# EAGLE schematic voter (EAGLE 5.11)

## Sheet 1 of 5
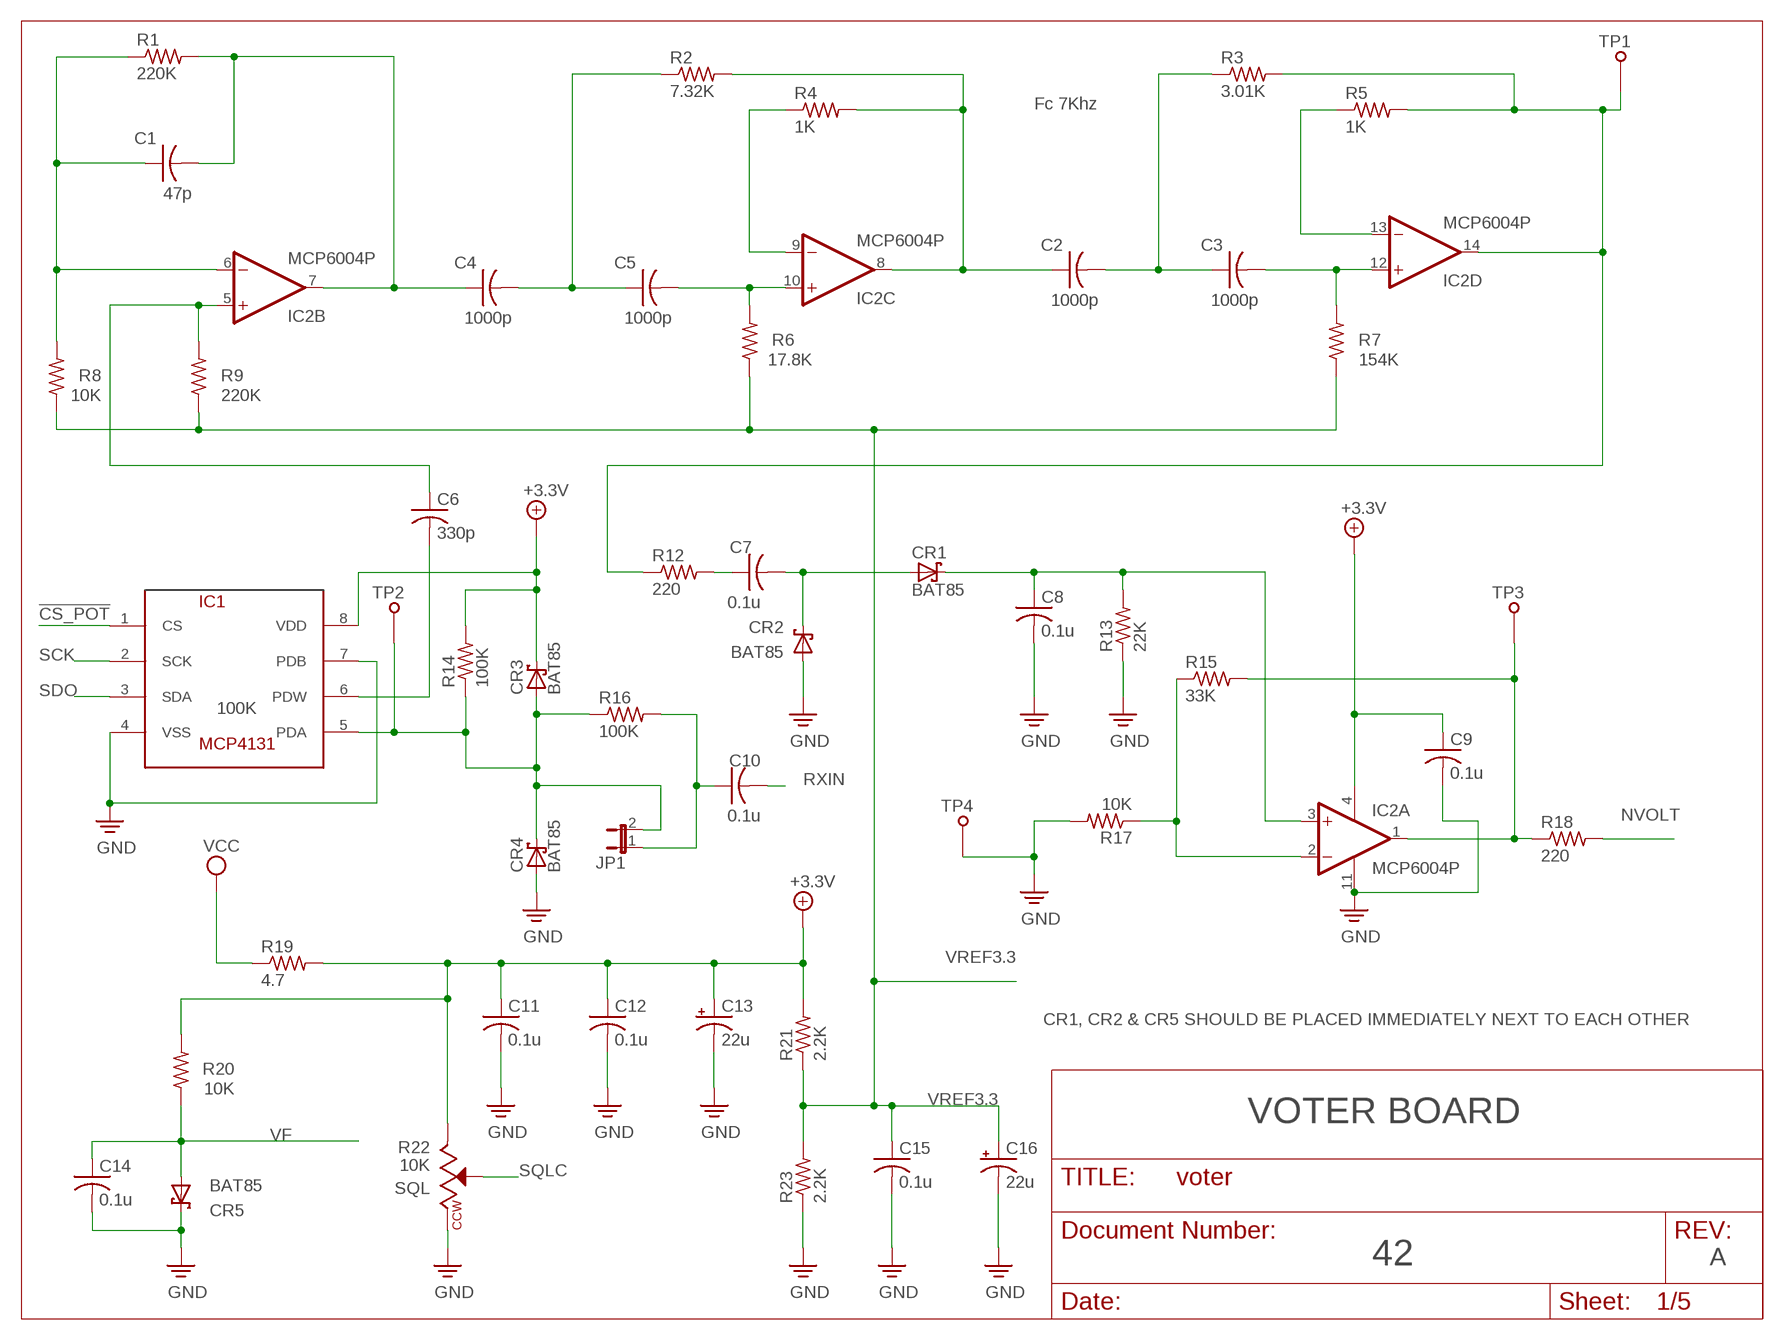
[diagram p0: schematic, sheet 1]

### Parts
C1  47p  C-US025-030X050  [C025-030X050]
C2  1000p  C-US025-030X050  [C025-030X050]
C3  1000p  C-US025-030X050  [C025-030X050]
C4  1000p  C-US025-030X050  [C025-030X050]
C5  1000p  C-US025-030X050  [C025-030X050]
C6  330p  C-US025-030X050  [C025-030X050]
C7  0.1u  C-US025-030X050  [C025-030X050]
C8  0.1u  C-US025-030X050  [C025-030X050]
C9  0.1u  C-US025-030X050  [C025-030X050]
C10  0.1u  C-US025-030X050  [C025-030X050]
C11  0.1u  C-US025-030X050  [C025-030X050]
C12  0.1u  C-US025-030X050  [C025-030X050]
C13  22u  CPOL-USE2-5  [E2-5]
C14  0.1u  C-US025-030X050  [C025-030X050]
C15  0.1u  C-US025-030X050  [C025-030X050]
C16  22u  CPOL-USE2-5  [E2-5]
CR1  BAT85  [DO34-7]
CR2  BAT85  [DO34-7]
CR3  BAT85  [DO34-7]
CR4  BAT85  [DO34-7]
CR5  BAT85  [DO34-7]
IC1  MCP4131  [DIL08]
IC2  MCP6004P  MCP604P  [DIL14]
JP1  JP1E  [JP1]
R1  220K  R-US_0207/10  [0207/10]
R2  7.32K  R-US_0207/10  [0207/10]
R3  3.01K  R-US_0207/10  [0207/10]
R4  1K  R-US_0207/10  [0207/10]
R5  1K  R-US_0207/10  [0207/10]
R6  17.8K  R-US_0207/10  [0207/10]
R7  154K  R-US_0207/10  [0207/10]
R8  10K  R-US_0207/10  [0207/10]
R9  220K  R-US_0207/10  [0207/10]
R12  220  R-US_0207/10  [0207/10]
R13  22K  R-US_0207/10  [0207/10]
R14  100K  R-US_0207/10  [0207/10]
R15  33K  R-US_0207/10  [0207/10]
R16  100K  R-US_0207/10  [0207/10]
R17  10K  R-US_0207/10  [0207/10]
R18  220  R-US_0207/10  [0207/10]
R19  4.7  R-US_0207/10  [0207/10]
R20  10K  R-US_0207/10  [0207/10]
R21  2.2K  R-US_0207/10  [0207/10]
R22  10K  BOURNS3296W  [BOURNS3296]
R23  2.2K  R-US_0207/10  [0207/10]
TP1  TESTPINTPSQ025  [TESTPIN]
TP2  TESTPINTPSQ025  [TESTPIN]
TP3  TESTPINTPSQ025  [TESTPIN]
TP4  TESTPINTPSQ025  [TESTPIN]

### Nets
!CS_POT: IC1.1(CS) ; also sheet 3
+3.3V [power]: C9.1 C11.1 C12.1 C13.+ CR3.C IC1.8(VDD) IC2.4(P:V+) R14.2 R19.2 R20.2 R21.2 R22.3 ; also sheet 2,3
FLTNOISE: IC2.14(D:OUT) R3.2 R5.2 R12.1 TP1.TP
GND: C8.2 C9.2 C11.2 C12.2 C13.- C14.2 C15.2 C16.- CR2.A CR4.A CR5.C IC1.4(VSS) IC1.7(PDB) IC2.11(P:V-) R13.1 R17.2 R22.1 R23.1 TP4.TP ; also sheet 2,3,4,5
N$1: IC2.2(A:-IN) R15.1 R17.1
N$3: C1.2 C4.1 IC2.7(B:OUT) R1.2
N$4: C4.2 C5.1 R2.1
N$5: C5.2 IC2.10(C:+IN) R6.2
N$6: C2.1 IC2.8(C:OUT) R2.2 R4.2
N$7: C2.2 C3.1 R3.1
N$8: C3.2 IC2.12(D:+IN) R7.2
N$9: C8.1 CR1.C IC2.3(A:+IN) R13.2
N$10: C1.1 IC2.6(B:-IN) R1.1 R8.2
N$11: C7.2 CR1.A CR2.C
N$12: IC2.13(D:-IN) R5.1
N$13: IC2.9(C:-IN) R4.1
N$14: CR3.A CR4.C IC1.5(PDA) JP1.2 R14.1 R16.1 TP2.TP
N$15: C10.1 JP1.1 R16.2
N$16: C7.1 R12.2
N$18: IC2.1(A:OUT) R15.2 R18.1 TP3.TP
N$19: C6.2 IC1.6(PDW)
N$23: C6.1 IC2.5(B:+IN) R9.2
NVOLT: R18.2 ; also sheet 3
RXIN: C10.2 ; also sheet 2,5
SCK: IC1.2(SCK) ; also sheet 3,4
SDO: IC1.3(SDA) ; also sheet 3,4
SQLC: R22.2 ; also sheet 3
VCC [power]: R19.1 ; also sheet 3,4,5
VF: C14.1 CR5.A R20.1 ; also sheet 3
VREF3.3: C15.1 C16.+ R6.1 R7.1 R8.1 R9.1 R21.1 R23.2 ; also sheet 2

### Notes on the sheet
- Fc 7Khz
- 100K
- VREF3.3
- CR1, CR2 & CR5 SHOULD BE PLACED IMMEDIATELY NEXT TO EACH OTHER
- VOTER BOARD
- SQL
- 42 | A

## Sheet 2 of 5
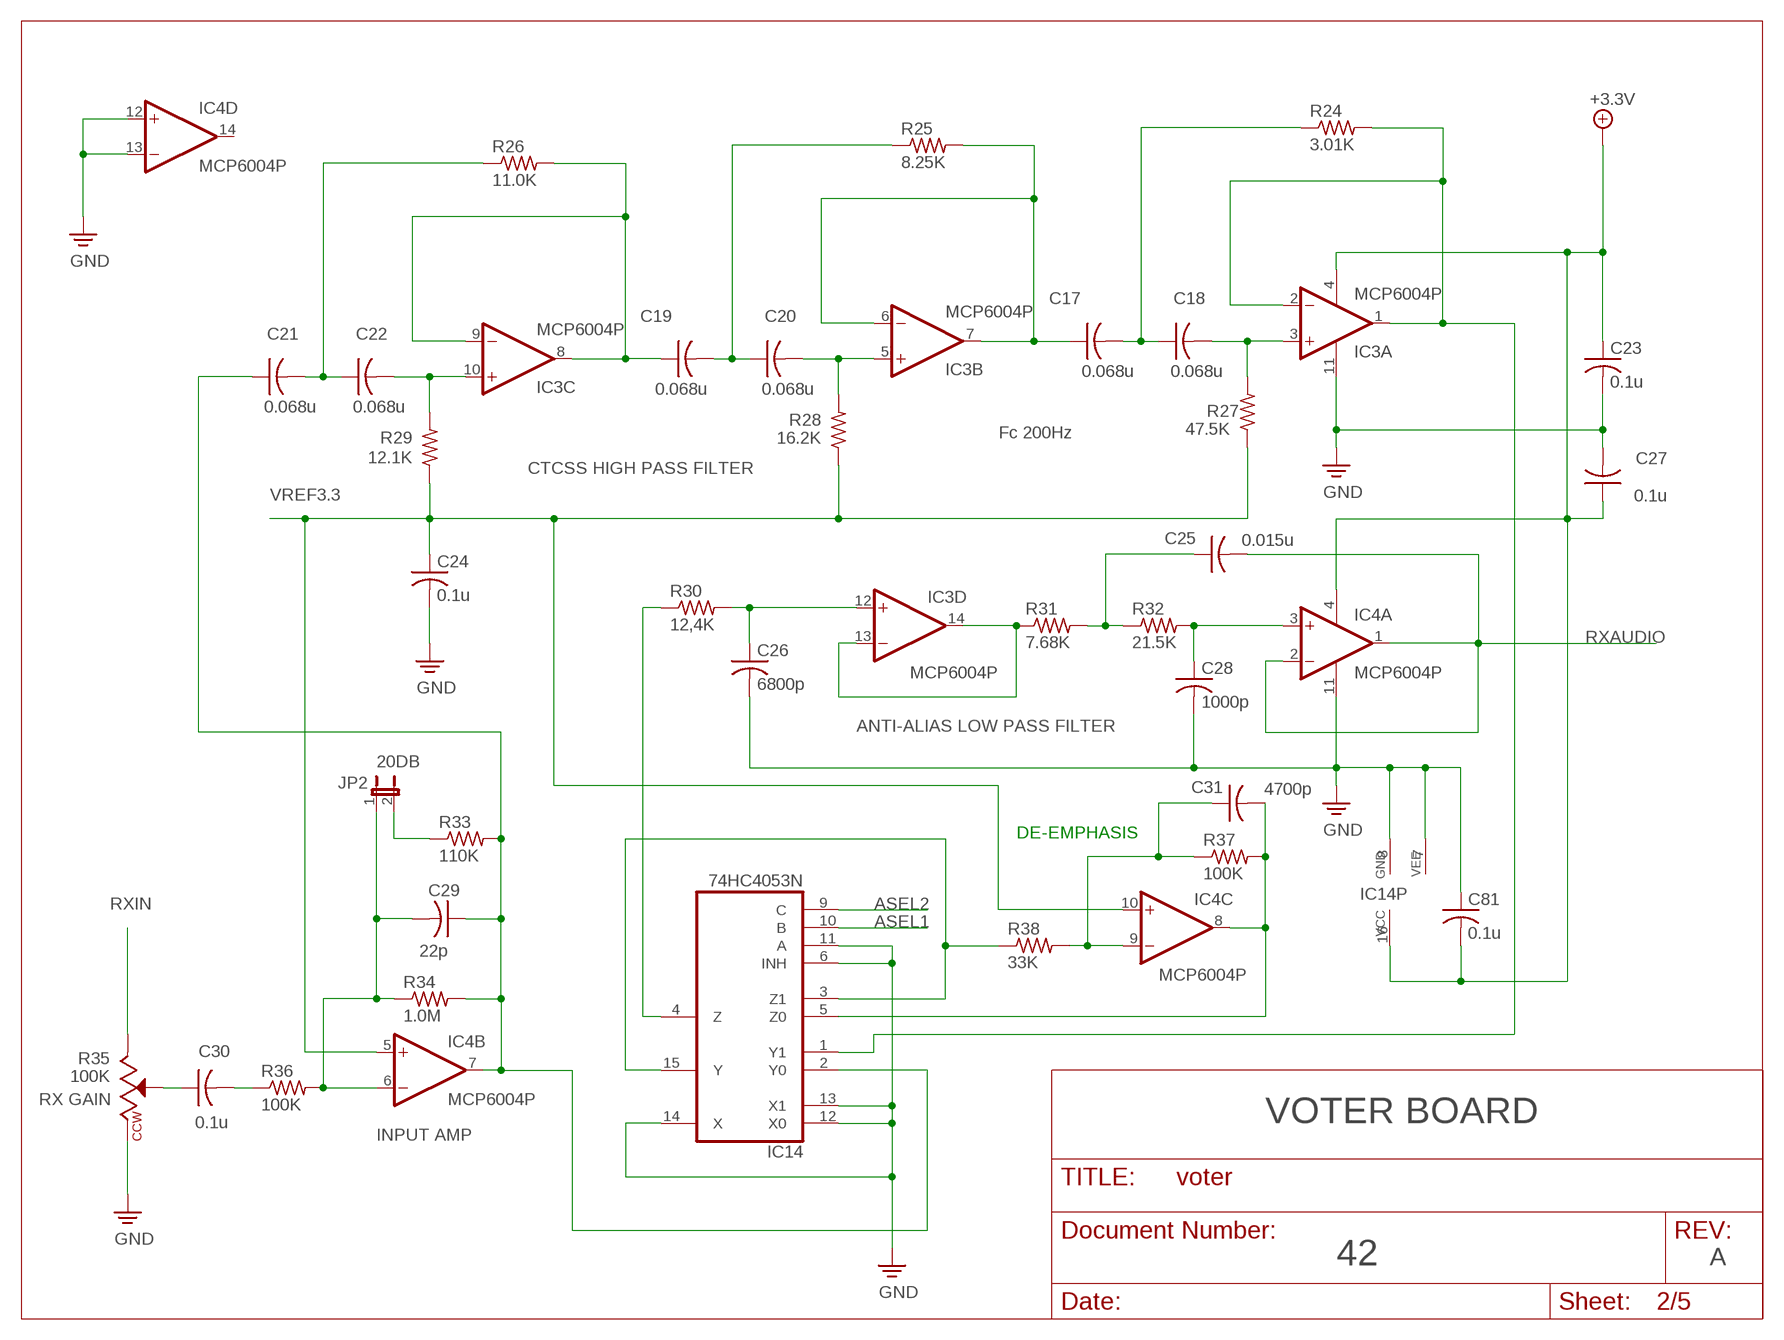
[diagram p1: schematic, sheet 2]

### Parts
C17  0.068u  C-US050-030X075  [C050-030X075]
C18  0.068u  C-US050-030X075  [C050-030X075]
C19  0.068u  C-US050-030X075  [C050-030X075]
C20  0.068u  C-US050-030X075  [C050-030X075]
C21  0.068u  C-US050-030X075  [C050-030X075]
C22  0.068u  C-US050-030X075  [C050-030X075]
C23  0.1u  C-US025-030X050  [C025-030X050]
C24  0.1u  C-US025-030X050  [C025-030X050]
C25  0.015u  C-US050-030X075  [C050-030X075]
C26  6800p  C-US050-030X075  [C050-030X075]
C27  0.1u  C-US025-030X050  [C025-030X050]
C28  1000p  C-US025-030X050  [C025-030X050]
C29  22p  C-US025-030X050  [C025-030X050]
C30  0.1u  C-US025-030X050  [C025-030X050]
C31  4700p  C-US050-030X075  [C050-030X075]
C81  0.1u  C-US025-030X050  [C025-030X050]
IC3  MCP6004P  MCP604P  [DIL14]
IC4  MCP6004P  MCP604P  [DIL14]
IC14  74HC4053N  4053N  [DIL16]
JP2  JP1E  [JP1]
R24  3.01K  R-US_0207/10  [0207/10]
R25  8.25K  R-US_0207/10  [0207/10]
R26  11.0K  R-US_0207/10  [0207/10]
R27  47.5K  R-US_0207/10  [0207/10]
R28  16.2K  R-US_0207/10  [0207/10]
R29  12.1K  R-US_0207/10  [0207/10]
R30  12,4K  R-US_0207/10  [0207/10]
R31  7.68K  R-US_0207/10  [0207/10]
R32  21.5K  R-US_0207/10  [0207/10]
R33  110K  R-US_0207/10  [0207/10]
R34  1.0M  R-US_0207/10  [0207/10]
R35  100K  BOURNS3296W  [BOURNS3296]
R36  100K  R-US_0207/10  [0207/10]
R37  100K  R-US_0207/10  [0207/10]
R38  33K  R-US_0207/10  [0207/10]

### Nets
+3.3V [power]: C23.1 C27.1 C81.2 IC3.4(P:V+) IC4.4(P:V+) IC14.16(VCC) ; also sheet 1,3
ASEL1: IC14.10(B) ; also sheet 3
ASEL2: IC14.9(C) ; also sheet 3
GND: C23.2 C24.2 C26.2 C27.2 C28.2 C81.1 IC3.11(P:V-) IC4.11(P:V-) IC4.12(D:+IN) IC4.13(D:-IN) IC14.6(INH) IC14.7(VEE) IC14.8(GND) IC14.11(A) IC14.12(X0) IC14.13(X1) IC14.14(X) R35.1 ; also sheet 1,3,4,5
N$17: C28.1 IC4.3(A:+IN) R32.2
N$24: IC3.1(A:OUT) IC3.2(A:-IN) IC14.1(Y1) R24.2
N$25: IC3.13(D:-IN) IC3.14(D:OUT) R31.1
N$26: C25.1 R31.2 R32.1
N$29: C30.1 R35.2
N$30: C26.1 IC3.12(D:+IN) R30.2
N$31: C30.2 R36.1
N$32: C29.2 IC4.6(B:-IN) JP2.1 R34.1 R36.2
N$34: JP2.2 R33.1
N$35: C31.1 IC4.9(C:-IN) R37.1 R38.2
N$36: C21.1 C29.1 IC4.7(B:OUT) IC14.2(Y0) R33.2 R34.2
N$52: C17.2 C18.1 R24.1
N$82: C18.2 IC3.3(A:+IN) R27.2
N$87: C17.1 IC3.6(B:-IN) IC3.7(B:OUT) R25.2
N$88: C19.2 C20.1 R25.1
N$89: C20.2 IC3.5(B:+IN) R28.2
N$90: C19.1 IC3.8(C:OUT) IC3.9(C:-IN) R26.2
N$91: C21.2 C22.1 R26.1
N$92: C22.2 IC3.10(C:+IN) R29.2
N$109: IC14.4(Z) R30.1
N$114: C31.2 IC4.8(C:OUT) IC14.5(Z0) R37.2
RXAUDIO: C25.2 IC4.1(A:OUT) IC4.2(A:-IN) ; also sheet 3
RXFLAT: IC14.3(Z1) IC14.15(Y) R38.1
RXIN: R35.3 ; also sheet 1,5
VREF3.3: C24.1 IC4.5(B:+IN) IC4.10(C:+IN) R27.1 R28.1 R29.1 ; also sheet 1
Unconnected: IC4.14(D:OUT)

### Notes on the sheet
- Fc 200Hz
- CTCSS HIGH PASS FILTER
- ANTI-ALIAS LOW PASS FILTER
- 20DB
- DE-EMPHASIS
- RX GAIN
- VOTER BOARD
- INPUT AMP
- 42 | A

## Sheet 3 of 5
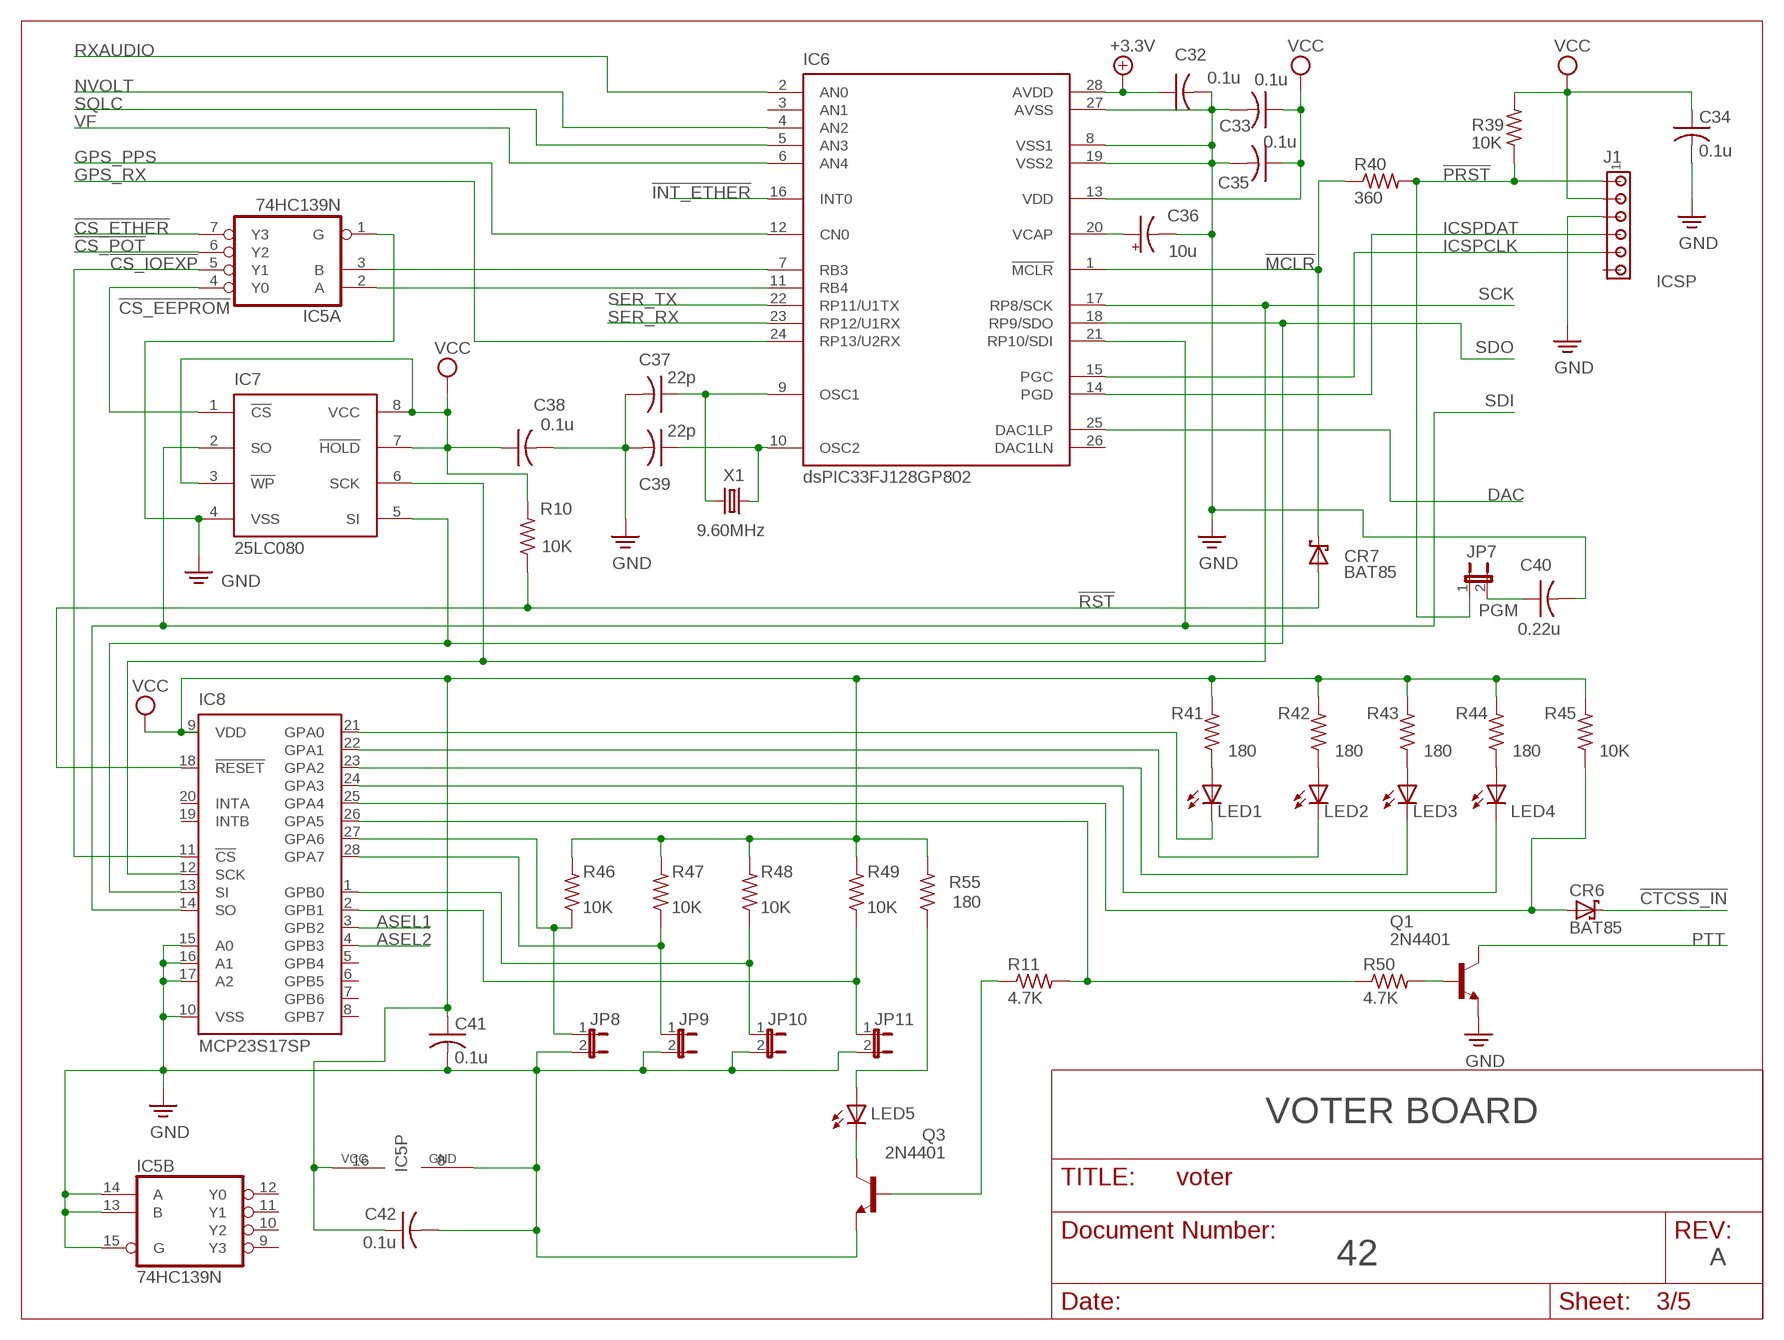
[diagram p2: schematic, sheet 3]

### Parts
C32  0.1u  C-US025-030X050  [C025-030X050]
C33  0.1u  C-US025-030X050  [C025-030X050]
C34  0.1u  C-US025-030X050  [C025-030X050]
C35  0.1u  C-US025-030X050  [C025-030X050]
C36  10u  CPOL-USE2-5  [E2-5]
C37  22p  C-US025-030X050  [C025-030X050]
C38  0.1u  C-US025-030X050  [C025-030X050]
C39  22p  C-US025-030X050  [C025-030X050]
C40  0.22u  C-US025-030X050  [C025-030X050]
C41  0.1u  C-US025-030X050  [C025-030X050]
C42  0.1u  C-US025-030X050  [C025-030X050]
CR6  BAT85  [DO34-7]
CR7  BAT85  [DO34-7]
IC5  74HC139N  74LS139N  [DIL16]
IC6  DSPIC33FJ128GP802  [DIL28-3]
IC7  25LC080  [DIL08]
IC8  MCP23S17SP  [DIL28-3]
J1  CONN-MTA100-6  [MTA6-100]
JP7  JP1E  [JP1]
JP8  JP1E  [JP1]
JP9  JP1E  [JP1]
JP10  JP1E  [JP1]
JP11  JP1E  [JP1]
LED1  LED3MM  [LED3MM]
LED2  LED3MM  [LED3MM]
LED3  LED3MM  [LED3MM]
LED4  LED3MM  [LED3MM]
LED5  LED3MM  [LED3MM]
Q1  2N4401  [TO92]
Q3  2N4401  [TO92]
R10  10K  R-US_0207/10  [0207/10]
R11  4.7K  R-US_0207/10  [0207/10]
R39  10K  R-US_0207/10  [0207/10]
R40  360  R-US_0207/10  [0207/10]
R41  180  R-US_0207/10  [0207/10]
R42  180  R-US_0207/10  [0207/10]
R43  180  R-US_0207/10  [0207/10]
R44  180  R-US_0207/10  [0207/10]
R45  10K  R-US_0207/10  [0207/10]
R46  10K  R-US_0207/10  [0207/10]
R47  10K  R-US_0207/10  [0207/10]
R48  10K  R-US_0207/10  [0207/10]
R49  10K  R-US_0207/10  [0207/10]
R50  4.7K  R-US_0207/10  [0207/10]
R55  180  R-US_0207/10  [0207/10]
X1  9.60MHz  TUNINGFORKXTAL  [TUNINGFORKXTAL]

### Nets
!CS_EEPROM [power]: IC5.4(A:Y0) IC7.1(!CS)
!CS_ETHER: IC5.7(A:Y3) ; also sheet 4
!CS_IOEXP: IC5.5(A:Y1) IC8.11(!CS)
!CS_POT: IC5.6(A:Y2) ; also sheet 1
!CTCSS_IN: CR6.C ; also sheet 5
!INT_ETHER: IC6.16(INT0) ; also sheet 4
!MCLR: CR7.C IC6.1(!MCLR) R40.1
!POT_CS: IC5.2(A:A) IC6.11(RB4)
!PRST: J1.1 JP7.1 R39.1 R40.2
!RST: CR7.A IC8.18(!RESET) R10.1 ; also sheet 4
+3.3V [power]: C32.1 IC6.28(AVDD) ; also sheet 1,2
ASEL1: IC8.3(GPB2) ; also sheet 2
ASEL2: IC8.4(GPB3) ; also sheet 2
DAC: IC6.25(DAC1LP) ; also sheet 5
GND: C32.2 C33.2 C34.2 C35.2 C36.- C37.2 C38.2 C39.2 C40.2 C41.2 C42.2 IC5.1(A:G) IC5.8(P:GND) IC5.13(B:B) IC5.14(B:A) IC5.15(B:G) IC6.8(VSS1) IC6.19(VSS2) IC6.27(AVSS) IC7.4(VSS) IC8.10(VSS) IC8.15(A0) IC8.16(A1) IC8.17(A2) J1.3 JP8.2 JP9.2 JP10.2 JP11.2 Q1.3(E) Q3.3(E) ; also sheet 1,2,4,5
GPS_PPS: IC6.12(CN0) ; also sheet 5
GPS_RX: IC6.24(RP13/U2RX) ; also sheet 5
ICSPCLK: IC6.15(PGC) J1.5
ICSPDAT: IC6.14(PGD) J1.4
N$33: C37.1 IC6.9(OSC1) X1.2
N$37: C39.1 IC6.10(OSC2) X1.1
N$38: C36.+ IC6.20(VCAP)
N$39: IC5.3(A:B) IC6.7(RB3)
N$40: Q1.2(B) R50.2
N$41: IC8.26(GPA5) R11.2 R50.1
N$42: IC8.21(GPA0) LED1.K(C)
N$43: IC8.22(GPA1) LED2.K(C)
N$44: LED1.A R41.1
N$45: LED2.A R42.1
N$46: LED3.A R43.1
N$47: LED4.A R44.1
N$48: IC8.23(GPA2) LED3.K(C)
N$49: IC8.24(GPA3) LED4.K(C)
N$50: IC8.2(GPB1) JP11.1 R49.1
N$51: IC8.1(GPB0) JP10.1 R48.1
N$53: IC8.28(GPA7) JP9.1 R47.1
N$54: IC8.27(GPA6) JP8.1 R46.1
N$56: LED5.K(C) Q3.1(C)
N$57: LED5.A R55.1
N$58: C40.1 JP7.2
N$59: Q3.2(B) R11.1
N$108: CR6.A IC8.25(GPA4) R45.1
NVOLT: IC6.4(AN2) ; also sheet 1
PTT: Q1.1(C) ; also sheet 5
RXAUDIO: IC6.2(AN0) ; also sheet 2
SCK: IC6.17(RP8/SCK) IC7.6(SCK) IC8.12(SCK) ; also sheet 1,4
SDI: IC6.21(RP10/SDI) IC7.2(SO) IC8.14(SO) ; also sheet 4
SDO: IC6.18(RP9/SDO) IC7.5(SI) IC8.13(SI) ; also sheet 1,4
SER_RX: IC6.23(RP12/U1RX) ; also sheet 4
SER_TX: IC6.22(RP11/U1TX) ; also sheet 4
SQLC: IC6.5(AN3) ; also sheet 1
VCC [power]: C33.1 C34.1 C35.1 C38.1 C41.1 C42.1 IC5.16(P:VCC) IC6.13(VDD) IC7.3(!WP) IC7.7(!HOLD) IC7.8(VCC) IC8.9(VDD) J1.2 R10.2 R39.2 R41.2 R42.2 R43.2 R44.2 R45.2 R46.2 R47.2 R48.2 R49.2 R55.2 ; also sheet 1,4,5
VF: IC6.6(AN4) ; also sheet 1
Unconnected: IC5.9(B:Y3) IC5.10(B:Y2) IC5.11(B:Y1) IC5.12(B:Y0) IC6.3(AN1) IC6.26(DAC1LN) IC8.5(GPB4) IC8.6(GPB5) IC8.7(GPB6) IC8.8(GPB7) IC8.19(INTB) IC8.20(INTA) J1.6

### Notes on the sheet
- ICSP
- PGM
- VOTER BOARD
- 42 | A

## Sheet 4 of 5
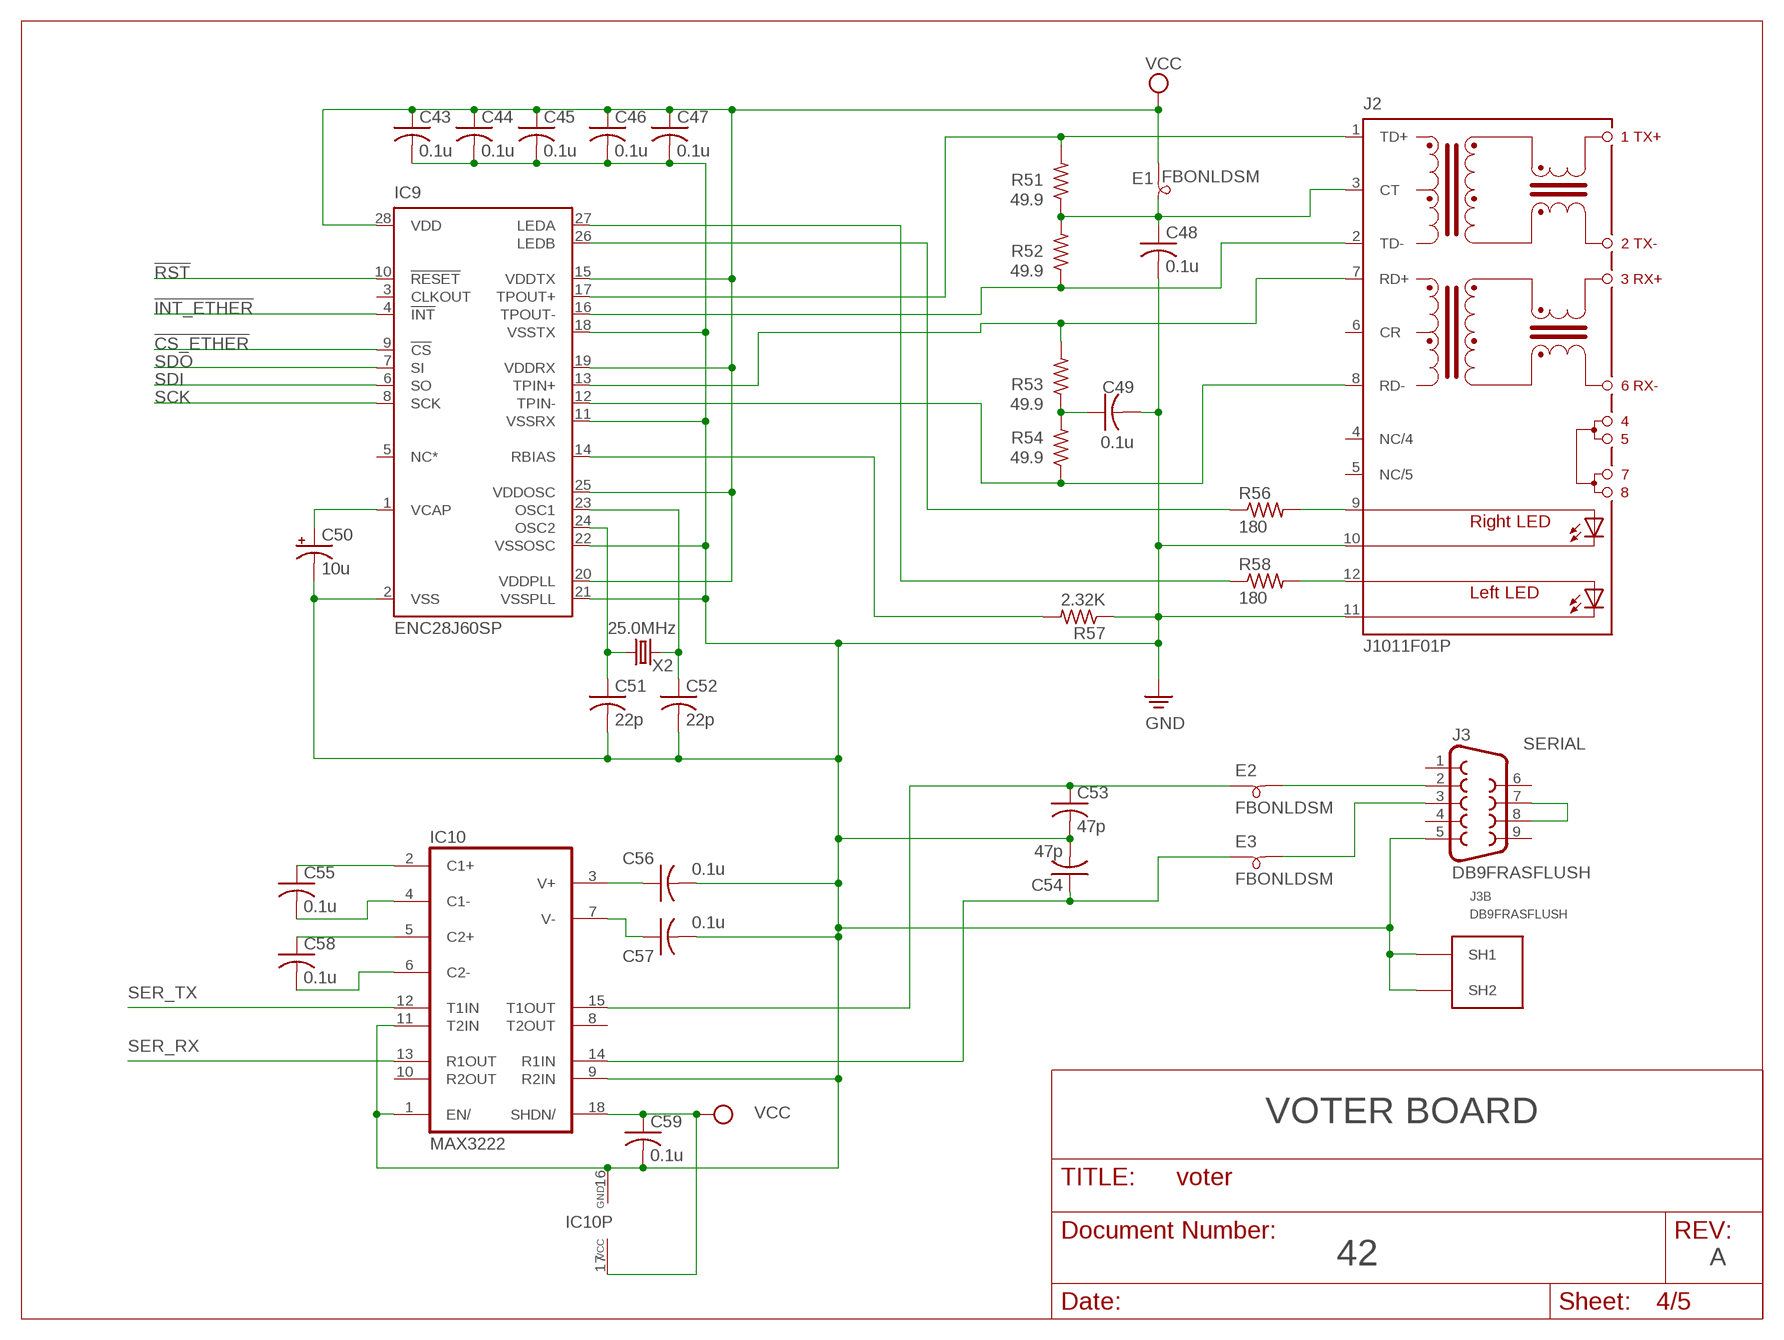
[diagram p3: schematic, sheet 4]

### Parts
C43  0.1u  C-US025-030X050  [C025-030X050]
C44  0.1u  C-US025-030X050  [C025-030X050]
C45  0.1u  C-US025-030X050  [C025-030X050]
C46  0.1u  C-US025-030X050  [C025-030X050]
C47  0.1u  C-US025-030X050  [C025-030X050]
C48  0.1u  C-US025-030X050  [C025-030X050]
C49  0.1u  C-US025-030X050  [C025-030X050]
C50  10u  CPOL-USE2-5  [E2-5]
C51  22p  C-US025-030X050  [C025-030X050]
C52  22p  C-US025-030X050  [C025-030X050]
C53  47p  C-US025-030X050  [C025-030X050]
C54  47p  C-US025-030X050  [C025-030X050]
C55  0.1u  C-US025-030X050  [C025-030X050]
C56  0.1u  C-US025-030X050  [C025-030X050]
C57  0.1u  C-US025-030X050  [C025-030X050]
C58  0.1u  C-US025-030X050  [C025-030X050]
C59  0.1u  C-US025-030X050  [C025-030X050]
E1  FBONLDSM  [FBONLEADSSMALL]
E2  FBONLDSM  [FBONLEADSSMALL]
E3  FBONLDSM  [FBONLEADSSMALL]
IC9  ENC28J60SP  [DIL28-3]
IC10  MAX3222  [DIL18]
J2  J1011F01P  J1006F01P  [J1]
J3  DB9FRASFLUSH  [DSUB9F]
R51  49.9  R-US_0207/10  [0207/10]
R52  49.9  R-US_0207/10  [0207/10]
R53  49.9  R-US_0207/10  [0207/10]
R54  49.9  R-US_0207/10  [0207/10]
R56  180  R-US_0207/10  [0207/10]
R57  2.32K  R-US_0207/10  [0207/10]
R58  180  R-US_0207/10  [0207/10]
X2  25.0MHz  TUNINGFORKXTAL  [TUNINGFORKXTAL]

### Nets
!CS_ETHER: IC9.9(!CS) ; also sheet 3
!INT_ETHER: IC9.4(!INT) ; also sheet 3
!RST: IC9.10(!RESET) ; also sheet 3
GND: C43.2 C44.2 C45.2 C46.2 C47.2 C48.2 C49.2 C50.- C51.2 C52.2 C53.2 C54.2 C56.2 C57.2 C59.2 IC9.2(VSS) IC9.11(VSSRX) IC9.18(VSSTX) IC9.21(VSSPLL) IC9.22(VSSOSC) IC10.1(EN/) IC10.9(R2IN) IC10.11(T2IN) IC10.16(GND) J2.10(C-R) J2.11(C-L) J3.5 J3.SHELL1(SH1) J3.SHELL2(SH2) R57.1 ; also sheet 1,2,3,5
N$2: J2.12(A-L) R58.2
N$21: C49.1 R53.1 R54.2
N$22: J2.9(A-R) R56.2
N$27: C55.1 IC10.2(C1+)
N$28: IC9.17(TPOUT+) J2.1(TD+) R51.2
N$60: IC9.16(TPOUT-) J2.2(TD-) R52.1
N$61: IC9.12(TPIN-) J2.8(RD-) R54.1
N$62: IC9.13(TPIN+) J2.7(RD+) R53.2
N$63: IC9.27(LEDA) R58.1
N$64: IC9.26(LEDB) R56.1
N$65: IC9.14(RBIAS) R57.2
N$66: C48.1 E1.1 J2.3(CT) R51.1 R52.2
N$67: C50.+ IC9.1(VCAP)
N$68: C52.1 IC9.23(OSC1) X2.2
N$69: C51.1 IC9.24(OSC2) X2.1
N$70: C57.1 IC10.7(V-)
N$71: C54.1 E3.1 IC10.14(R1IN)
N$72: C56.1 IC10.3(V+)
N$74: C55.2 IC10.4(C1-)
N$75: C58.1 IC10.5(C2+)
N$76: C58.2 IC10.6(C2-)
N$77: E2.2 J3.2
N$78: E3.2 J3.3
N$80: C53.1 E2.1 IC10.15(T1OUT)
N$83: J3.7 J3.8
SCK: IC9.8(SCK) ; also sheet 1,3
SDI: IC9.6(SO) ; also sheet 3
SDO: IC9.7(SI) ; also sheet 1,3
SER_RX: IC10.13(R1OUT) ; also sheet 3
SER_TX: IC10.12(T1IN) ; also sheet 3
VCC [power]: C43.1 C44.1 C45.1 C46.1 C47.1 C59.1 E1.2 IC9.15(VDDTX) IC9.19(VDDRX) IC9.20(VDDPLL) IC9.25(VDDOSC) IC9.28(VDD) IC10.17(VCC) IC10.18(SHDN/) ; also sheet 1,3,5
Unconnected: IC9.3(CLKOUT) IC9.5(NC*) IC10.8(T2OUT) IC10.10(R2OUT) J2.4(NC/4) J2.5(NC/5) J2.6(CR) J3.1 J3.4 J3.6 J3.9

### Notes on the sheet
- SERIAL
- VOTER BOARD
- 42 | A

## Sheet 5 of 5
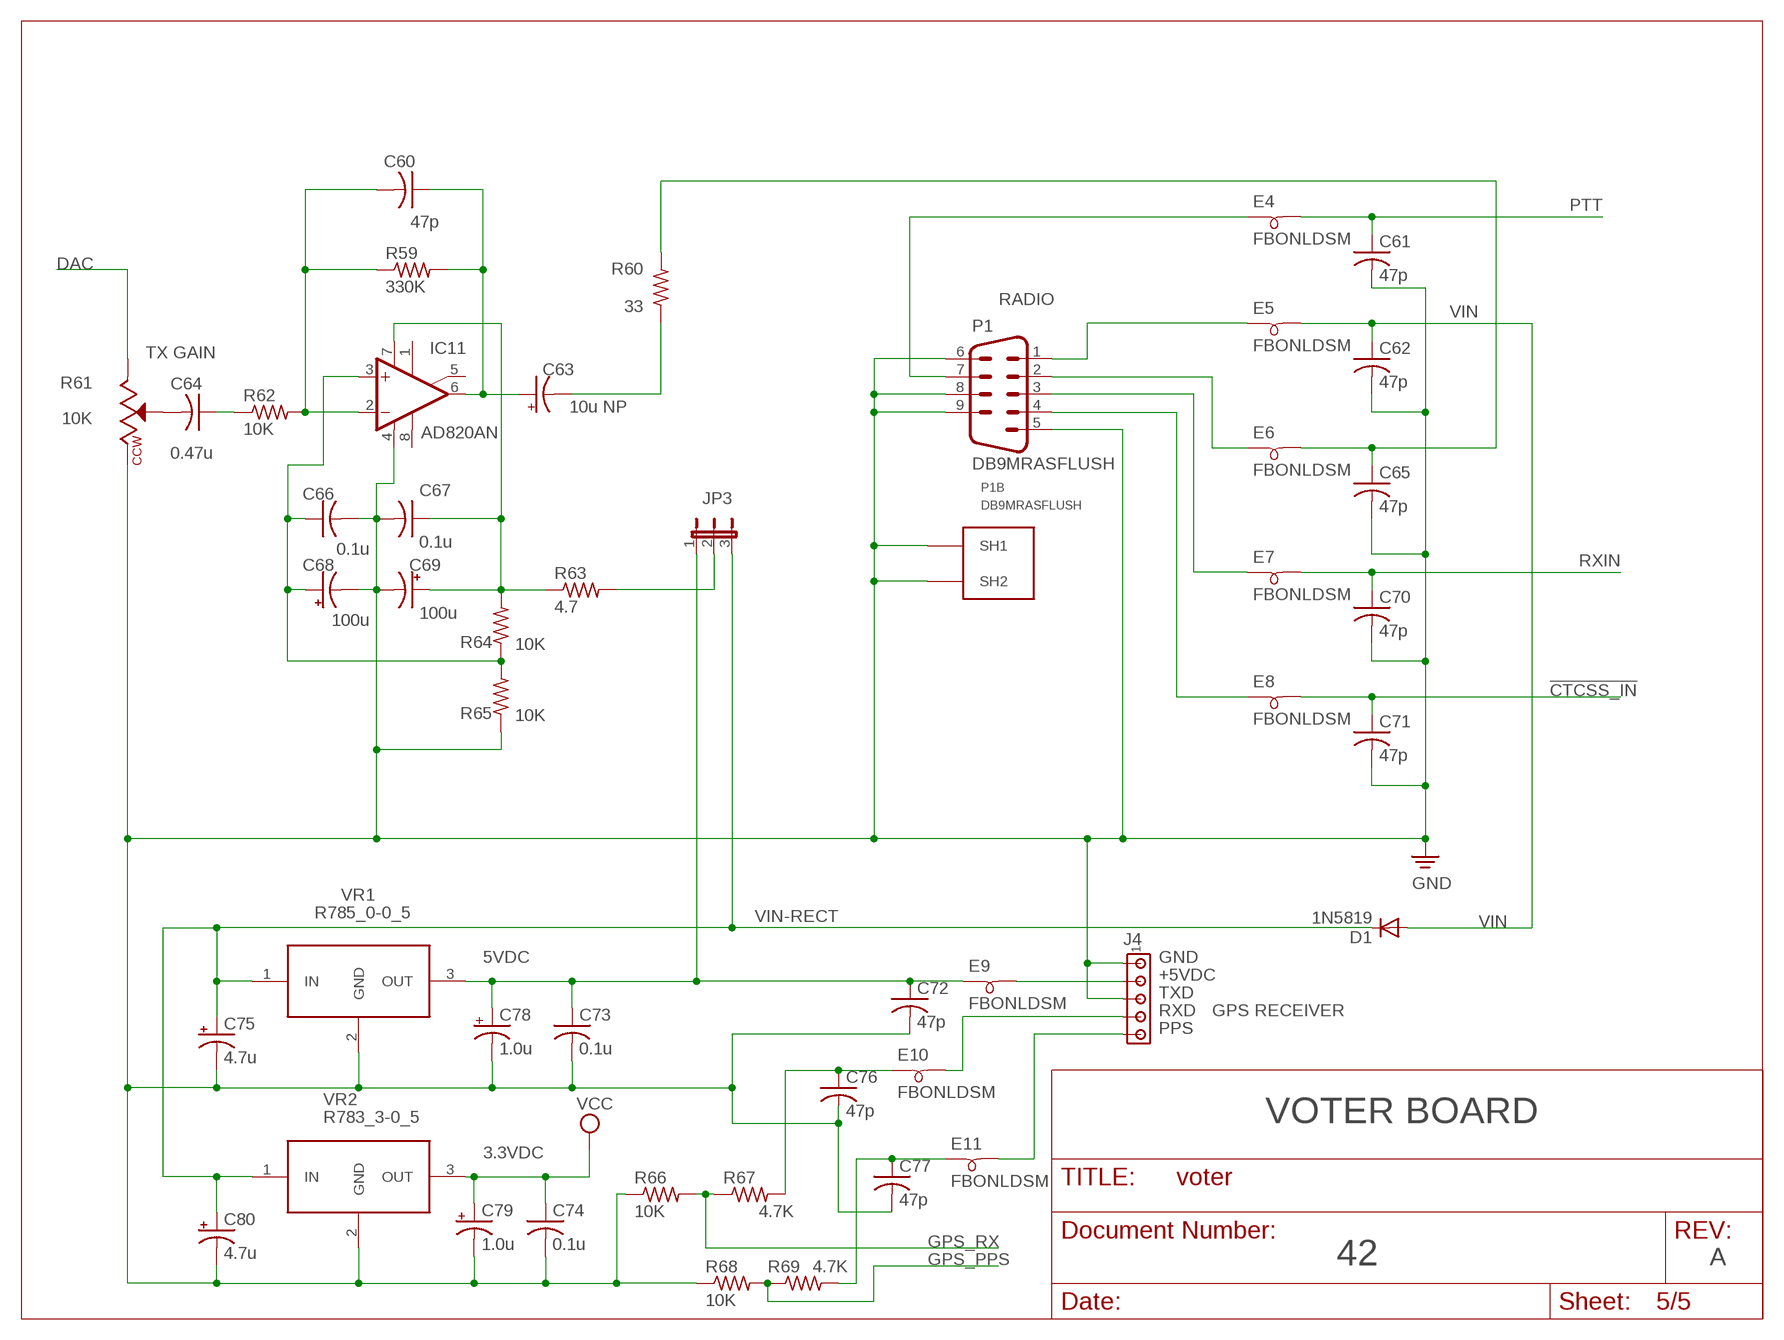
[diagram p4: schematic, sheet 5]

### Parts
C60  47p  C-US025-030X050  [C025-030X050]
C61  47p  C-US025-030X050  [C025-030X050]
C62  47p  C-US025-030X050  [C025-030X050]
C63  10u NP  CPOL-USE2-5  [E2-5]
C64  0.47u  C-US025-030X050  [C025-030X050]
C65  47p  C-US025-030X050  [C025-030X050]
C66  0.1u  C-US025-030X050  [C025-030X050]
C67  0.1u  C-US025-030X050  [C025-030X050]
C68  100u  CPOL-USE2.5-7  [E2,5-7]
C69  100u  CPOL-USE2.5-7  [E2,5-7]
C70  47p  C-US025-030X050  [C025-030X050]
C71  47p  C-US025-030X050  [C025-030X050]
C72  47p  C-US025-030X050  [C025-030X050]
C73  0.1u  C-US025-030X050  [C025-030X050]
C74  0.1u  C-US025-030X050  [C025-030X050]
C75  4.7u  CPOL-USE2-5  [E2-5]
C76  47p  C-US025-030X050  [C025-030X050]
C77  47p  C-US025-030X050  [C025-030X050]
C78  1.0u  CPOL-USE2-5  [E2-5]
C79  1.0u  CPOL-USE2-5  [E2-5]
C80  4.7u  CPOL-USE2-5  [E2-5]
D1  1N5819  1N4004  [DO41-10]
E4  FBONLDSM  [FBONLEADSSMALL]
E5  FBONLDSM  [FBONLEADSSMALL]
E6  FBONLDSM  [FBONLEADSSMALL]
E7  FBONLDSM  [FBONLEADSSMALL]
E8  FBONLDSM  [FBONLEADSSMALL]
E9  FBONLDSM  [FBONLEADSSMALL]
E10  FBONLDSM  [FBONLEADSSMALL]
E11  FBONLDSM  [FBONLEADSSMALL]
IC11  AD820AN  TL081P  [DIL08]
J4  CONN-MTA100-5  [MTA5-100]
JP3  JP2E  [JP2]
P1  DB9MRASFLUSH  [DSUB9M]
R59  330K  R-US_0207/10  [0207/10]
R60  33  R-US_0207/10  [0207/10]
R61  10K  BOURNS3296W  [BOURNS3296]
R62  10K  R-US_0207/10  [0207/10]
R63  4.7  R-US_0207/10  [0207/10]
R64  10K  R-US_0207/10  [0207/10]
R65  10K  R-US_0207/10  [0207/10]
R66  10K  R-US_0207/10  [0207/10]
R67  4.7K  R-US_0207/10  [0207/10]
R68  10K  R-US_0207/10  [0207/10]
R69  4.7K  R-US_0207/10  [0207/10]
VR1  R785_0-0_5  R785R0-0R5  [R-78XX]
VR2  R783_3-0_5  R785R0-0R5  [R-78XX]

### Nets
!CTCSS_IN: C71.1 E8.2 ; also sheet 3
DAC: R61.3 ; also sheet 3
GND: C61.2 C62.2 C65.2 C66.2 C67.2 C68.- C69.- C70.2 C71.2 C72.2 C73.2 C74.2 C75.- C76.2 C77.2 C78.- C79.- C80.- IC11.4(V-) J4.1 J4.3 P1.5 P1.6 P1.8 P1.9 P1.G1(SH1) P1.G2(SH2) R61.1 R65.1 R66.1 R68.1 VR1.2(GND) VR2.2(GND) ; also sheet 1,2,3,4
GPS_PPS: R68.2 R69.1 ; also sheet 3
GPS_RX: R66.2 R67.1 ; also sheet 3
N$20 [power]: E9.2 J4.2
N$55: JP3.2 R63.2
N$73: C64.1 R62.1
N$79: C63.- R60.1
N$81: C64.2 R61.2
N$84: C65.1 E6.2 R60.2
N$85: C67.1 C69.+ IC11.7(V+) R63.1 R64.2
N$86: C60.2 IC11.2(-IN) R59.1 R62.2
N$93: E4.1 P1.7
N$94: E5.1 P1.1
N$96: E7.1 P1.3
N$97: E8.1 P1.4
N$98: E6.1 P1.2
N$99: C60.1 C63.+ IC11.6(OUT) R59.2
N$100: C66.1 C68.+ IC11.3(+IN) R64.1 R65.2
N$102 [power]: C72.1 C73.1 C78.+ E9.1 JP3.1 VR1.3(OUT)
N$103: C76.1 E10.1 R67.2
N$104: E11.2 J4.5
N$105: C77.1 E11.1 R69.2
N$107: E10.2 J4.4
PTT: C61.1 E4.2 ; also sheet 3
RXIN: C70.1 E7.2 ; also sheet 1,2
VCC [power]: C74.1 C79.+ VR2.3(OUT) ; also sheet 1,3,4
VIN [power]: C62.1 D1.A E5.2
VIN-RECT [power]: C75.+ C80.+ D1.C JP3.3 VR1.1(IN) VR2.1(IN)
Unconnected: IC11.1(ON1) IC11.5(ON2) IC11.8(OPT)

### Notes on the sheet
- RADIO
- TX GAIN
- 5VDC | GND
- +5VDC
- TXD
- RXD | GPS RECEIVER
- PPS
- VOTER BOARD
- 3.3VDC
- 42 | A

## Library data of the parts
C1-C12 C14 C15 C17-C35 C37-C49 C53-C62 C64-C67 C70-C74 C76 C77 C81 = rcl:C-US: CAPACITOR, American symbol
C13 C16 C36 C50 C63 C68 C69 C75 C78-C80 = rcl:CPOL-US: POLARIZED CAPACITOR, American symbol
C51 C52 = resistor:C-US: CAPACITOR, American symbol
CR1-CR7 = custom:BAT85: BAT85 Schottky Diode
D1 = diode:1N4004: DIODE
E1-E11 = custom:FBONLDSM
IC1 = custom:MCP4131: MICROCHIP DIG POT SPI DIP8
IC2-IC4 = linear:MCP604: Quad Op Amp 2.7V to 6.0V Single Supply CMOS Source: http://ww1.microchip.com/downloads/en/DeviceDoc/21314g.pdf
IC5 = 74xx-us:74*139: Dual 2-line to 4-line DECODER/DEMULTIPLEXER
IC6 = custom:DSPIC33FJ128GP802: MICROCHIP DSPIC PIC PROCESSOR
IC7 = custom:25LC080: MICROCHIP SPI EEPROM 8K
IC8 = microchip:MCP23S17: http://ww1.microchip.com/downloads/en/DeviceDoc/21952a.pdf Source: http://ww1.microchip.com/downloads/en/DeviceDoc/21952a.pdf; MF: MICROCHIP; MPN: MCP23S17-E/SP; OC_FARNELL: 1292238; OC_NEWARK: 31K2951
IC9 = microchip:ENC28J60: Stand-Alone Ethernet Controller with SPI Interface Source: http://ww1.microchip.com/downloads/en/DeviceDoc/39662c.pdf; MF: MICROCHIP; MPN: ENC28J60/SP; OC_FARNELL: 1084619; OC_NEWARK: 96K3661
IC10 = maxim:MAX3222: RS232 TRANSEIVER; MPN: MAX3222EPN+; OC_FARNELL: 1188044; OC_NEWARK: 99K3237
IC11 = linear:TL081: OP AMP
IC14 = 40xx:4053: Triple 2-channel ANALOG MULTIPLEXER
J1 = qrp:CONN-MTA100-6: 6 PIN AMP MTA-100 series connector, vertical
J2 = con-pulse:J1006F01P: PULSEJACK (TM) 1x1 Tab-UP RJ45 10/100 Base-TX RJ45 1x1 Tab-UP with LEDs 8-pin (J1 series) and 6-pin (JP series) integrated magnetics connector, designed to support applications, such as ADSL modems, LAN-on-Motherboard, and Hub and Switches. Source: www.pulseeng.com .. PulseJack-J402.pdf; OC_FARNELL: unknown; OC_NEWARK: unknown
J3 = custom:DB9FRAS: DB9 Female Right Angle Connector 0.318
J4 = qrp:CONN-MTA100-5: AMP MTA100 5 pin polarized header
JP1 JP2 JP7-JP11 = jumper:JP1E: JUMPER
JP3 = jumper:JP2E: JUMPER
LED1-LED5 = led:LED: LED
P1 = custom:DB9MRAS: DB9 Male Right Angle 0.318
Q1 Q3 = custom:2N4401: NPN Transistor
R1-R10 R12-R21 R23 R37 R38 R46-R49 R59 R62 R66 R68 R69 = rcl:R-US_: RESISTOR, American symbol
R11 R24-R34 R36 R39-R45 R50-R58 R60 R63-R65 R67 = resistor:R-US_: RESISTOR, American symbol
R22 R35 R61 = qrp:BOURNS3296W: Bourns 3296W series multi-turn pot Top Adjust
TP1-TP4 = custom:TESTPIN: Test pin assortment
VR1 VR2 = recom:R785R0-0R5: 2.5W 5V Switching Regulator
X1 X2 = custom:TUNINGFORKXTAL: Tuning Fork Crystal

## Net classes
0 default: width 0.203 mm, drill 0.508 mm, clearance 0.203 mm
1 power: width 0.635 mm, drill 0.508 mm, clearance 0.203 mm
